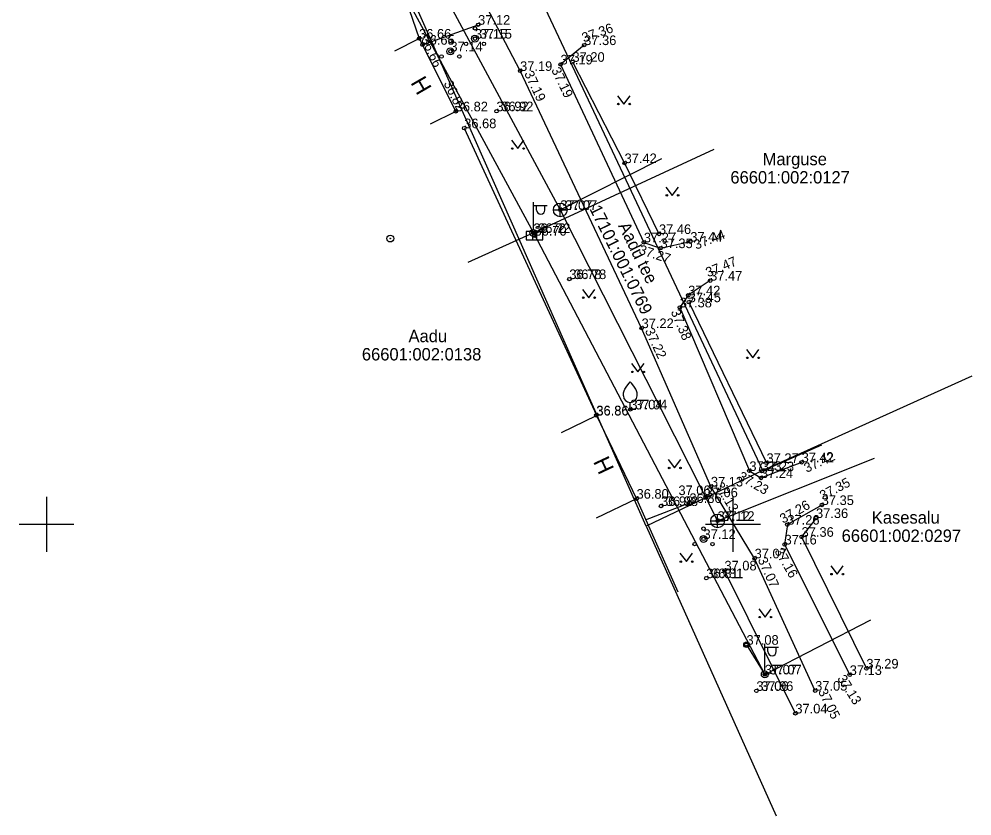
# Model space of a CAD drawing. Extents: x 627548 to 628052, y 6467984 to 6468802.
# Drawn here: x 627648 to 627717.4, y 6468278.8 to 6468336.8 of the extents above; entities that cross this region are included whole.
import ezdxf

# ---------------------------------------------------------------- set-up
doc = ezdxf.new("R2010")
doc.units = 0
for name, color, linetype in [('AED', 7, 'Continuous'), ('ELRAJATISMP', 7, 'Continuous'), ('HALJASTUS', 7, 'Continuous'), ('HOONE', 7, 'Continuous'), ('KKAEV', 7, 'Continuous'), ('KORGUS-EH2000', 7, 'Continuous'), ('KTRASS', 7, 'Continuous'), ('MOOTKORG-EH2000', 7, 'Continuous'), ('MOOTMPUNKT', 7, 'Continuous'), ('MPOHULIIN', 7, 'Continuous'), ('PIIR', 7, 'Continuous'), ('POST', 7, 'Continuous'), ('PUU', 7, 'Continuous'), ('SIOHULIIN', 7, 'Continuous'), ('TEE', 7, 'Continuous'), ('VORK', 7, 'Continuous')]:
    doc.layers.add(name, color=color, linetype=linetype)

msp = doc.modelspace()

# ---------------------------------------------------------------- linework, layer by layer
at = {"layer": 'AED'}
for p, q in [((627677.387, 6468334.946), (627681.434, 6468336.401)), ((627680.423, 6468328.862), (627690.05, 6468307.948)), ((627702.106, 6468303.871), (627706.476, 6468305.8)), ((627692.977, 6468301.869), (627695.974, 6468295.078)), ((627693.64, 6468300.317), (627696.83, 6468301.558)), ((627697.886, 6468302.1), (627697.886, 6468301.85)), ((627697.886, 6468302.1), (627698.136, 6468302.1)), ((627697.886, 6468301.85), (627698.136, 6468301.85)), ((627698.136, 6468302.1), (627698.136, 6468301.85))]:
    msp.add_line(p, q, dxfattribs=at)
msp.add_lwpolyline([(627670.805, 6468342.532), (627673.658, 6468343.687), (627676.168, 6468338.238), (627677.141, 6468335.391)], dxfattribs=at)
at = {"layer": 'ELRAJATISMP'}
for p, q in [((627686.14, 6468321.332), (627684.946, 6468321.332)), ((627684.946, 6468321.332), (627684.946, 6468320.736)), ((627685.407, 6468321.332), (627685.407, 6468320.736)), ((627685.679, 6468321.332), (627685.679, 6468320.736)), ((627686.14, 6468320.736), (627686.14, 6468321.332)), ((627684.946, 6468320.736), (627686.14, 6468320.736))]:
    msp.add_line(p, q, dxfattribs=at)
at = {"layer": 'HALJASTUS'}
for p, q in [((627691.591, 6468331.23), (627692.055, 6468330.624)), ((627692.055, 6468330.624), (627692.5, 6468331.23)), ((627683.858, 6468327.987), (627684.321, 6468327.38)), ((627684.321, 6468327.38), (627684.767, 6468327.987)), ((627695.117, 6468324.573), (627695.581, 6468323.967)), ((627695.581, 6468323.967), (627696.026, 6468324.573)), ((627689.032, 6468317.119), (627689.496, 6468316.513)), ((627689.496, 6468316.513), (627689.941, 6468317.119)), ((627696.776, 6468316.187), (627702.443, 6468304.475)), ((627700.974, 6468312.738), (627701.438, 6468312.132)), ((627701.438, 6468312.132), (627701.883, 6468312.738)), ((627692.615, 6468311.714), (627693.078, 6468311.107)), ((627693.078, 6468311.107), (627693.524, 6468311.714)), ((627695.288, 6468304.715), (627695.751, 6468304.109)), ((627695.751, 6468304.109), (627696.197, 6468304.715)), ((627696.141, 6468297.888), (627696.604, 6468297.281)), ((627696.604, 6468297.281), (627697.05, 6468297.888)), ((627707.116, 6468296.977), (627707.58, 6468296.371)), ((627707.58, 6468296.371), (627708.025, 6468296.977)), ((627704.543, 6468286.222), (627699.379, 6468296.642)), ((627701.884, 6468293.848), (627702.348, 6468293.241)), ((627702.348, 6468293.241), (627702.793, 6468293.848))]:
    msp.add_line(p, q, dxfattribs=at)
for points in [[(627688.311, 6468333.7), (627692.104, 6468326.319), (627694.608, 6468321.156)], [(627706.047, 6468300.46), (627704.998, 6468299.092), (627709.716, 6468289.494)]]:
    msp.add_lwpolyline(points, dxfattribs=at)
for centre in [(627691.654, 6468330.624), (627692.483, 6468330.624), (627683.92, 6468327.38), (627684.749, 6468327.38), (627695.18, 6468323.967), (627696.008, 6468323.967), (627689.095, 6468316.513), (627689.924, 6468316.513), (627701.037, 6468312.132), (627701.866, 6468312.132), (627692.677, 6468311.107), (627693.506, 6468311.107), (627695.35, 6468304.109), (627696.179, 6468304.109), (627696.203, 6468297.281), (627697.032, 6468297.281), (627707.178, 6468296.371), (627708.007, 6468296.371), (627701.947, 6468293.241), (627702.776, 6468293.241)]:
    msp.add_circle(centre, 0.055, dxfattribs=at)
at = {"layer": 'HOONE'}
for points in [[(627675.375, 6468334.503), (627677.139, 6468335.392), (627679.809, 6468330.091), (627677.952, 6468329.156)], [(627687.51, 6468306.697), (627690.053, 6468307.925), (627692.977, 6468301.869), (627690.045, 6468300.453)]]:
    msp.add_lwpolyline(points, dxfattribs=at)
at = {"layer": 'KKAEV'}
for p, q in [((627687.419, 6468322.41), (627687.419, 6468323.41)), ((627686.919, 6468322.91), (627687.919, 6468322.91)), ((627698.377, 6468300.252), (627699.377, 6468300.252)), ((627698.877, 6468299.752), (627698.877, 6468300.752))]:
    msp.add_line(p, q, dxfattribs=at)
for centre in [(627687.419, 6468322.91), (627698.877, 6468300.252)]:
    msp.add_circle(centre, 0.5, dxfattribs=at)
at = {"layer": 'KTRASS'}
for p, q in [((627687.419, 6468322.91), (627694.826, 6468326.653)), ((627687.419, 6468322.91), (627698.877, 6468300.252)), ((627698.877, 6468300.252), (627710.319, 6468304.824))]:
    msp.add_line(p, q, dxfattribs=at)
msp.add_lwpolyline([(627669.837, 6468355.594), (627687.419, 6468322.91)], dxfattribs=at)
at = {"layer": 'MOOTMPUNKT'}
for centre in [(627681.434, 6468336.401), (627677.139, 6468335.392), (627677.387, 6468334.946), (627681.207, 6468335.387), (627689.161, 6468334.92), (627679.419, 6468334.46), (627687.441, 6468333.508), (627688.311, 6468333.7), (627684.494, 6468333.036), (627679.809, 6468330.091), (627682.773, 6468330.099), (627680.423, 6468328.862), (627692.104, 6468326.319), (627687.419, 6468322.91), (627685.459, 6468321.228), (627685.543, 6468321.034), (627694.608, 6468321.156), (627693.508, 6468320.543), (627696.891, 6468320.596), (627694.723, 6468320.124), (627688.078, 6468317.869), (627698.336, 6468317.757), (627696.736, 6468316.686), (627696.776, 6468316.187), (627696.122, 6468315.807), (627693.344, 6468314.297), (627692.522, 6468308.374), (627690.05, 6468307.948), (627690.053, 6468307.925), (627702.443, 6468304.475), (627705.003, 6468304.52), (627701.194, 6468303.891), (627702.106, 6468303.871), (627702.035, 6468303.377), (627698.392, 6468302.759), (627692.977, 6468301.869), (627696.83, 6468301.558), (627698.011, 6468301.975), (627706.464, 6468301.407), (627694.759, 6468301.333), (627698.877, 6468300.252), (627706.047, 6468300.46), (627703.96, 6468299.977), (627697.856, 6468298.937), (627704.998, 6468299.092), (627703.759, 6468298.532), (627701.575, 6468297.521), (627699.379, 6468296.642), (627698.059, 6468296.077), (627700.985, 6468291.226), (627702.316, 6468289.064), (627708.502, 6468289.026), (627709.716, 6468289.494), (627701.704, 6468287.866), (627705.987, 6468287.879), (627704.543, 6468286.222)]:
    msp.add_circle(centre, 0.125, dxfattribs=at)
at = {"layer": 'MPOHULIIN'}
for points in [[(627668.977, 6468351.69), (627685.459, 6468321.228)], [(627685.459, 6468321.228), (627698.626, 6468327.339)], [(627685.459, 6468321.228), (627680.69, 6468319.066)], [(627685.459, 6468321.228), (627702.316, 6468289.064)], [(627702.316, 6468289.064), (627710.047, 6468293.044)]]:
    msp.add_lwpolyline(points, dxfattribs=at)
at = {"layer": 'PIIR'}
for p, q in [((627693.67, 6468299.87), (627664.45, 6468365.98)), ((627702.17, 6468303.93), (627685.55, 6468339.27)), ((627717.405, 6468310.786), (627702.17, 6468303.93)), ((627702.17, 6468303.93), (627693.67, 6468299.87)), ((627693.67, 6468299.87), (627703.148, 6468278.752))]:
    msp.add_line(p, q, dxfattribs=at)
at = {"layer": 'POST'}
for p, q in [((627685.467, 6468321.473), (627685.467, 6468323.473)), ((627685.467, 6468323.223), (627686.467, 6468323.223)), ((627685.694, 6468322.902), (627685.694, 6468323.223)), ((627686.306, 6468322.902), (627686.306, 6468323.223)), ((627702.318, 6468289.301), (627702.318, 6468291.301)), ((627702.318, 6468291.051), (627703.318, 6468291.051)), ((627702.545, 6468290.73), (627702.545, 6468291.051)), ((627703.157, 6468290.73), (627703.157, 6468291.051))]:
    msp.add_line(p, q, dxfattribs=at)
msp.add_lwpolyline([(627700.985, 6468291.226), (627702.316, 6468289.064)], dxfattribs=at)
for centre, radius in [((627675.037, 6468320.824), 0.25), ((627685.459, 6468321.228), 0.25), ((627685.459, 6468321.228), 0.0234), ((627675.037, 6468320.824), 0.0234), ((627700.985, 6468291.226), 0.2), ((627702.316, 6468289.064), 0.25), ((627702.316, 6468289.064), 0.0234)]:
    msp.add_circle(centre, radius, dxfattribs=at)
for centre in [(627686, 6468322.902), (627702.851, 6468290.73)]:
    msp.add_arc(centre, 0.306, 180, 0, dxfattribs=at)
at = {"layer": 'PUU'}
for p, q in [((627692.522, 6468308.374), (627692.522, 6468308.874)), ((627692.922, 6468308.374), (627692.522, 6468308.374))]:
    msp.add_line(p, q, dxfattribs=at)
for points in [[(627692.022, 6468309.374), (627692.022, 6468309.524), (627692.032, 6468309.589), (627692.067, 6468309.719), (627692.127, 6468309.839), (627692.272, 6468310.074), (627692.432, 6468310.279), (627692.522, 6468310.374)], [(627693.022, 6468309.374), (627693.022, 6468309.524), (627693.012, 6468309.589), (627692.977, 6468309.719), (627692.917, 6468309.839), (627692.772, 6468310.074), (627692.612, 6468310.279), (627692.522, 6468310.374)]]:
    msp.add_lwpolyline(points, dxfattribs=at)
for centre, radius in [((627681.207, 6468336.137), 0.125), ((627681.207, 6468335.387), 0.25), ((627679.419, 6468335.21), 0.125), ((627680.557, 6468335.012), 0.125), ((627681.857, 6468335.012), 0.125), ((627678.769, 6468334.085), 0.125), ((627679.419, 6468334.46), 0.25), ((627680.069, 6468334.085), 0.125), ((627697.856, 6468299.687), 0.125), ((627697.856, 6468298.937), 0.25), ((627697.206, 6468298.562), 0.125), ((627698.506, 6468298.562), 0.125)]:
    msp.add_circle(centre, radius, dxfattribs=at)
msp.add_arc((627692.522, 6468309.374), 0.5, 180, 0, dxfattribs=at)
at = {"layer": 'SIOHULIIN'}
for points in [[(627668.977, 6468351.69), (627685.459, 6468321.228)], [(627685.459, 6468321.228), (627702.316, 6468289.064)]]:
    msp.add_lwpolyline(points, dxfattribs=at)
at = {"layer": 'TEE'}
for points in [[(627705.987, 6468287.879), (627701.575, 6468297.521), (627698.392, 6468302.759), (627693.344, 6468314.297), (627684.494, 6468333.036), (627679.367, 6468342.859), (627675.577, 6468349.845), (627672.084, 6468355.605), (627669.957, 6468356.207), (627668.244, 6468355.634), (627666.883, 6468354.283)], [(627689.161, 6468334.92), (627687.441, 6468333.508), (627693.508, 6468320.543), (627694.723, 6468320.124), (627696.891, 6468320.596)], [(627698.336, 6468317.757), (627696.736, 6468316.686), (627696.122, 6468315.807), (627701.194, 6468303.891), (627702.035, 6468303.377), (627705.003, 6468304.52)], [(627706.464, 6468301.407), (627703.96, 6468299.977), (627703.759, 6468298.532), (627708.502, 6468289.026)]]:
    msp.add_lwpolyline(points, dxfattribs=at)
at = {"layer": 'VORK'}
for p, q in [((627650, 6468302), (627650, 6468298)), ((627700, 6468302), (627700, 6468298)), ((627648, 6468300), (627652, 6468300)), ((627698, 6468300), (627702, 6468300))]:
    msp.add_line(p, q, dxfattribs=at)

# ---------------------------------------------------------------- texts
at = {"layer": 'HOONE'}
for rotation, p in [(300.04836, (627676.483, 6468332.186)), (295.09108, (627689.795, 6468304.58))]:
    msp.add_text('H', height=1.2, rotation=rotation, dxfattribs=at).set_placement(p)
at = {"layer": 'KORGUS-EH2000'}
for s, rotation, p in [('37.36', 19.62679, (627689.135, 6468335.097)), ('36.66', 294.61284, (627677.259, 6468335.35)), ('37.19', 294.94118, (627684.78, 6468332.855)), ('37.19', 295.47901, (627686.748, 6468333.112)), ('36.82', 296.21316, (627678.908, 6468332.127)), ('37.44', 21.3936, (627697.316, 6468320.006)), ('37.27', 341.90824, (627693.093, 6468319.727)), ('37.47', 22.79247, (627698.188, 6468317.993)), ('37.38', 292.67112, (627695.455, 6468315.496)), ('37.22', 295.19928, (627693.567, 6468314.109)), ('37.42', 24.44034, (627705.366, 6468303.749)), ('37.23', 330.24298, (627700.308, 6468303.291)), ('37.13', 301.05212, (627698.651, 6468302.813)), ('37.35', 27.57376, (627706.54, 6468301.737)), ('37.26', 29.85253, (627703.655, 6468300.037)), ('37.16', 299.73652, (627703.002, 6468298.048)), ('37.07', 294.23345, (627701.788, 6468297.429)), ('37.13', 302.22364, (627707.568, 6468288.763)), ('37.05', 296.22938, (627706.176, 6468287.834))]:
    msp.add_text(s, height=0.7, rotation=rotation, dxfattribs=at).set_placement(p)
for s, p in [('37.15', (627681.557, 6468335.387)), ('36.92', (627683.123, 6468330.099)), ('37.07', (627687.769, 6468322.91)), ('36.72', (627685.809, 6468321.228)), ('36.78', (627688.428, 6468317.869)), ('37.04', (627692.872, 6468308.374)), ('37.06', (627696.027, 6468302.131)), ('36.98', (627695.109, 6468301.333)), ('37.12', (627699.227, 6468300.252)), ('36.81', (627698.409, 6468296.077)), ('37.07', (627702.666, 6468289.064)), ('37.06', (627702.054, 6468287.866))]:
    msp.add_text(s, height=0.7, dxfattribs=at).set_placement(p)
at = {"layer": 'MOOTKORG-EH2000'}
for s, p in [('37.12', (627681.434, 6468336.401)), ('36.66', (627677.139, 6468335.392)), ('36.65', (627677.387, 6468334.946)), ('37.15', (627681.207, 6468335.387)), ('37.36', (627689.161, 6468334.92)), ('37.14', (627679.419, 6468334.46)), ('37.19', (627687.441, 6468333.508)), ('37.20', (627688.311, 6468333.7)), ('37.19', (627684.494, 6468333.036)), ('36.82', (627679.809, 6468330.091)), ('36.92', (627682.773, 6468330.099)), ('36.68', (627680.423, 6468328.862)), ('37.42', (627692.104, 6468326.319)), ('37.07', (627687.419, 6468322.91)), ('36.72', (627685.459, 6468321.228)), ('36.70', (627685.543, 6468321.034)), ('37.46', (627694.608, 6468321.156)), ('37.27', (627693.508, 6468320.543)), ('37.44', (627696.891, 6468320.596)), ('37.35', (627694.723, 6468320.124)), ('36.78', (627688.078, 6468317.869)), ('37.47', (627698.336, 6468317.757)), ('37.42', (627696.736, 6468316.686)), ('37.45', (627696.776, 6468316.187)), ('37.38', (627696.122, 6468315.807)), ('37.22', (627693.344, 6468314.297)), ('36.86', (627690.05, 6468307.948)), ('36.86', (627690.053, 6468307.925)), ('37.04', (627692.522, 6468308.374)), ('37.27', (627702.443, 6468304.475)), ('37.42', (627705.003, 6468304.52)), ('37.23', (627701.194, 6468303.891)), ('37.23', (627702.106, 6468303.871)), ('37.24', (627702.035, 6468303.377)), ('37.13', (627698.392, 6468302.759)), ('36.80', (627692.977, 6468301.869)), ('36.86', (627696.83, 6468301.558)), ('37.06', (627698.011, 6468301.975)), ('36.98', (627694.759, 6468301.333)), ('37.35', (627706.464, 6468301.407)), ('37.12', (627698.877, 6468300.252)), ('37.36', (627706.047, 6468300.46)), ('37.26', (627703.96, 6468299.977)), ('37.12', (627697.856, 6468298.937)), ('37.36', (627704.998, 6468299.092)), ('37.16', (627703.759, 6468298.532)), ('37.07', (627701.575, 6468297.521)), ('37.08', (627699.379, 6468296.642)), ('36.81', (627698.059, 6468296.077)), ('37.08', (627700.985, 6468291.226)), ('37.07', (627702.316, 6468289.064)), ('37.13', (627708.502, 6468289.026)), ('37.29', (627709.716, 6468289.494)), ('37.06', (627701.704, 6468287.866)), ('37.05', (627705.987, 6468287.879)), ('37.04', (627704.543, 6468286.222))]:
    msp.add_text(s, height=0.7, dxfattribs=at).set_placement(p)
at = {"layer": 'PIIR'}
for s, p in [('Marguse', (627702.161, 6468326.165)), ('66601:002:0127', (627699.811, 6468324.835)), ('Aadu', (627676.368, 6468313.272)), ('66601:002:0138', (627672.97, 6468311.942)), ('Kasesalu', (627710.111, 6468300.051)), ('66601:002:0297', (627707.914, 6468298.721))]:
    msp.add_text(s, height=0.9, dxfattribs=at).set_placement(p)
for s, p in [('17101:001:0769', (627689.523, 6468323)), ('Aadu tee', (627691.621, 6468321.754))]:
    msp.add_text(s, height=0.9, rotation=296.23087, dxfattribs=at).set_placement(p)

doc.saveas('drawing.dxf')
